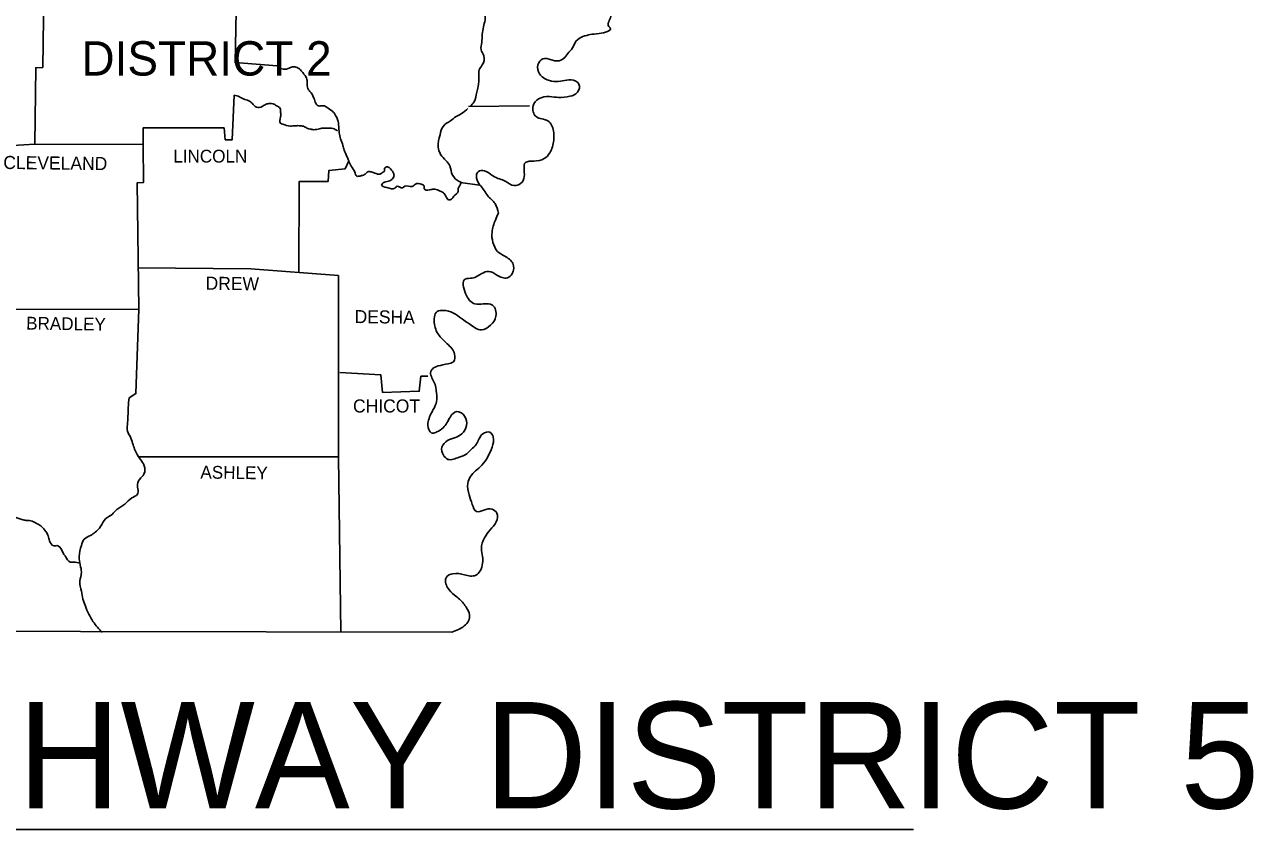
# Model space of a CAD drawing. Extents: x 1212896 to 1368412, y 378476 to 478763.
# Drawn here: x 1348211 to 1368412, y 441567 to 454801 of the extents above; entities that cross this region are included whole.
import ezdxf

# ---------------------------------------------------------------- set-up
doc = ezdxf.new("R2010")
doc.units = 0
doc.layers.add('R_Draft', color=7, linetype='Continuous')

msp = doc.modelspace()

# ---------------------------------------------------------------- linework, layer by layer
at = {"layer": 'R_Draft'}
for p, q in [((1355510, 453452), (1356510, 453467)), ((1355690, 452162), (1355375, 452202)), ((1329763, 441567), (1362824, 441567))]:
    msp.add_line(p, q, dxfattribs=at)
for points in [[(1348540, 456117), (1348510, 454097), (1348395, 454092), (1348380, 452837)], [(1351711, 456139), (1351670, 454177), (1352365, 454122)], [(1351655, 453642), (1351625, 452907), (1351510, 452907), (1351490, 453102), (1350160, 453102), (1350160, 452822)], [(1347650, 452792), (1348380, 452837)], [(1348380, 452837), (1350150, 452827)], [(1350160, 452827), (1350165, 452202), (1350060, 452197), (1350090, 450122)], [(1353540, 452562), (1353480, 452427), (1353215, 452402), (1353200, 452222), (1352725, 452222), (1352720, 450727)], [(1350075, 450802), (1351930, 450787), (1353370, 450677)], [(1353370, 450677), (1353370, 447687), (1353410, 444812)], [(1347830, 450117), (1350090, 450122)], [(1350090, 450122), (1350040, 448732), (1349930, 448662)], [(1353395, 449082), (1354065, 449042), (1354095, 448752), (1354700, 448772), (1354725, 449017), (1354840, 449017)], [(1355235, 444812), (1336910, 444842), (1336900, 448887)], [(1350088, 447692), (1353370, 447692)]]:
    msp.add_lwpolyline(points, dxfattribs=at)
for points in [[(1359445, 458317), (1359330, 458172), (1359160, 458262), (1359160, 458382), (1359185, 458507), (1359125, 458587), (1359020, 458552), (1359020, 458397), (1359010, 458247), (1358980, 458032), (1359050, 457967), (1359210, 457947), (1359325, 457917), (1359395, 457802), (1359390, 457662), (1359335, 457527), (1359255, 457417), (1359130, 457377), (1359030, 457442), (1358990, 457572), (1358945, 457687), (1358860, 457772), (1358770, 457677), (1358750, 457502), (1358755, 457352), (1358755, 457147), (1358885, 457012), (1358965, 456857), (1358940, 456717), (1358845, 456552), (1358805, 456407), (1358765, 456212), (1358770, 455997), (1358735, 455787), (1358665, 455647), (1358535, 455532), (1358450, 455457), (1358380, 455382), (1358345, 455232), (1358320, 455127), (1358225, 455002), (1358150, 454992), (1358090, 455042), (1358070, 455127), (1358070, 455212), (1358030, 455297), (1357905, 455332), (1357805, 455327), (1357760, 455257), (1357825, 455062), (1357850, 454937), (1357815, 454767), (1357835, 454747), (1357655, 454652), (1357510, 454637), (1357390, 454602), (1357275, 454527), (1357220, 454417), (1357140, 454327), (1357070, 454242), (1356975, 454202), (1356870, 454222), (1356730, 454237), (1356650, 454137), (1356675, 453992), (1356770, 453907), (1356910, 453867), (1357055, 453877), (1357195, 453892), (1357325, 453822), (1357300, 453687), (1357175, 453622), (1356990, 453602), (1356840, 453617), (1356660, 453577), (1356570, 453462), (1356620, 453287), (1356815, 453217), (1356905, 453052), (1356910, 452897), (1356845, 452692), (1356755, 452597), (1356580, 452557), (1356445, 452532), (1356425, 452302), (1356365, 452187), (1356260, 452152), (1356110, 452227), (1356020, 452262), (1355910, 452312), (1355770, 452397), (1355665, 452382), (1355695, 452162), (1355705, 452152), (1355825, 451987), (1355945, 451857), (1356000, 451702)], [(1359445, 458317), (1359330, 458172), (1359160, 458262), (1359160, 458382), (1359185, 458507), (1359125, 458587), (1359020, 458552), (1359020, 458397), (1359010, 458247), (1358980, 458032), (1359050, 457967), (1359210, 457947), (1359325, 457917), (1359395, 457802), (1359390, 457662), (1359335, 457527), (1359255, 457417), (1359130, 457377), (1359030, 457442), (1358990, 457572), (1358945, 457687), (1358860, 457772), (1358770, 457677), (1358750, 457502), (1358755, 457352), (1358755, 457147), (1358885, 457012), (1358965, 456857), (1358940, 456717), (1358845, 456552), (1358805, 456407), (1358765, 456212), (1358770, 455997), (1358735, 455787), (1358665, 455647), (1358535, 455532), (1358450, 455457), (1358380, 455382), (1358345, 455232), (1358320, 455127), (1358225, 455002), (1358150, 454992), (1358090, 455042), (1358070, 455127), (1358070, 455212), (1358030, 455297), (1357905, 455332), (1357805, 455327), (1357760, 455257), (1357825, 455062), (1357850, 454937), (1357815, 454767), (1357835, 454747), (1357655, 454652), (1357510, 454637), (1357390, 454602), (1357275, 454527), (1357220, 454417), (1357140, 454327), (1357070, 454242), (1356975, 454202), (1356870, 454222), (1356730, 454237), (1356650, 454137), (1356675, 453992), (1356770, 453907), (1356910, 453867), (1357055, 453877), (1357195, 453892), (1357325, 453822), (1357300, 453687), (1357175, 453622), (1356990, 453602), (1356840, 453617), (1356660, 453577), (1356570, 453462), (1356620, 453287), (1356815, 453217), (1356905, 453052), (1356910, 452897), (1356845, 452692), (1356755, 452597), (1356580, 452557), (1356445, 452532), (1356425, 452302), (1356365, 452187), (1356260, 452152), (1356110, 452227), (1356020, 452262), (1355910, 452312), (1355770, 452397), (1355665, 452382), (1355695, 452162), (1355705, 452152), (1355825, 451987), (1355945, 451857), (1356000, 451702)], [(1355535, 453452), (1355600, 453532), (1355645, 453687), (1355665, 453782), (1355680, 453947), (1355685, 454057), (1355735, 454137), (1355760, 454287), (1355715, 454387), (1355725, 454507), (1355735, 454642), (1355755, 454762), (1355780, 454877), (1355780, 454952), (1355715, 455052), (1355615, 455117), (1355535, 455142), (1355485, 455177), (1355415, 455237), (1355345, 455357), (1355305, 455402), (1355225, 455507), (1355145, 455567), (1355095, 455702), (1355015, 455797), (1354905, 455837), (1354825, 455922), (1354795, 456052), (1354745, 456132), (1354675, 456182), (1354560, 456252), (1354475, 456302), (1354450, 456417), (1354400, 456472), (1354280, 456502), (1354265, 456707)], [(1352365, 454122), (1352440, 454072), (1352545, 454077), (1352615, 454107), (1352670, 454102), (1352745, 454057), (1352795, 453997), (1352830, 453952), (1352855, 453882), (1352855, 453817), (1352880, 453727), (1352910, 453692), (1352950, 453627), (1352975, 453567), (1352990, 453527), (1353045, 453462), (1353095, 453467), (1353140, 453462), (1353200, 453427), (1353290, 453357), (1353305, 453337), (1353365, 453207), (1353375, 453127), (1353385, 453022), (1353405, 452922), (1353445, 452812), (1353465, 452737), (1353510, 452632), (1353540, 452562), (1353580, 452472), (1353640, 452372), (1353665, 452312), (1353750, 452317), (1353810, 452342), (1353855, 452382), (1353910, 452377), (1353970, 452357), (1354050, 452342), (1354100, 452372), (1354125, 452392), (1354130, 452437), (1354175, 452462), (1354225, 452427), (1354280, 452347), (1354280, 452297), (1354260, 452267), (1354195, 452227), (1354105, 452197), (1354080, 452162), (1354165, 452122), (1354300, 452112), (1354335, 452142), (1354425, 452117), (1354460, 452142), (1354580, 452137), (1354635, 452177), (1354745, 452172), (1354780, 452147), (1354780, 452102), (1354870, 452082), (1354935, 452097), (1355020, 452072), (1355095, 452032), (1355135, 451977), (1355185, 451917), (1355230, 451932), (1355265, 451977), (1355340, 452057), (1355340, 452107), (1355360, 452142), (1355385, 452192)], [(1351655, 453642), (1351745, 453612), (1351810, 453577), (1351895, 453547), (1351950, 453507), (1352025, 453442), (1352115, 453452), (1352180, 453492), (1352245, 453502), (1352295, 453497), (1352350, 453467), (1352410, 453422), (1352420, 453357), (1352420, 453282), (1352420, 453177), (1352455, 453162), (1352580, 453132), (1352665, 453137), (1352745, 453137), (1352810, 453122), (1352865, 453092), (1352905, 453082), (1352965, 453072), (1353015, 453077), (1353100, 453097), (1353150, 453097), (1353230, 453097), (1353280, 453092), (1353355, 453052)], [(1355390, 452207), (1355355, 452222), (1355245, 452327), (1355200, 452477), (1355140, 452562), (1355050, 452667), (1355010, 452787), (1355040, 452987), (1355095, 453132), (1355210, 453217), (1355305, 453287), (1355395, 453337), (1355500, 453422)], [(1356000, 451702), (1355950, 451587), (1355895, 451387), (1355910, 451217), (1355985, 451072), (1356105, 450992), (1356235, 450877), (1356225, 450702), (1356150, 450637), (1355975, 450682), (1355840, 450742), (1355725, 450707), (1355570, 450632), (1355455, 450617), (1355460, 450377), (1355615, 450207), (1355750, 450207), (1355905, 450187), (1355960, 450007), (1355870, 449857), (1355720, 449782), (1355530, 449872), (1355395, 449967), (1355260, 450057), (1355090, 450102), (1354995, 450082), (1354950, 449872), (1355030, 449682), (1355160, 449552), (1355280, 449382), (1355260, 449257), (1355170, 449222), (1355010, 449187), (1354915, 449137), (1354890, 449097), (1354940, 448927), (1354985, 448742), (1354985, 448602), (1354930, 448472), (1354845, 448272), (1354855, 448142), (1354915, 448082), (1354990, 448102), (1355090, 448172), (1355155, 448252), (1355210, 448352), (1355315, 448437), (1355445, 448362), (1355475, 448207), (1355400, 448072), (1355295, 448012), (1355165, 447962), (1355070, 447852), (1355095, 447722), (1355170, 447652), (1355355, 447687), (1355480, 447742), (1355550, 447812), (1355635, 447897), (1355680, 447982), (1355745, 448072), (1355860, 448097), (1355915, 448022), (1355895, 447852), (1355825, 447692), (1355730, 447557), (1355625, 447462), (1355495, 447257), (1355520, 447067), (1355570, 446912), (1355640, 446792), (1355760, 446817), (1355895, 446832), (1355975, 446767), (1355965, 446627), (1355865, 446492), (1355770, 446362), (1355720, 446182), (1355740, 446057), (1355740, 445942), (1355700, 445817), (1355630, 445747), (1355445, 445752), (1355250, 445772), (1355145, 445712), (1355165, 445542), (1355280, 445417), (1355360, 445352), (1355475, 445212), (1355525, 445097), (1355510, 444997), (1355440, 444912), (1355235, 444812)], [(1356000, 451702), (1355950, 451587), (1355895, 451387), (1355910, 451217), (1355985, 451072), (1356105, 450992), (1356235, 450877), (1356225, 450702), (1356150, 450637), (1355975, 450682), (1355840, 450742), (1355725, 450707), (1355570, 450632), (1355455, 450617), (1355460, 450377), (1355615, 450207), (1355750, 450207), (1355905, 450187), (1355960, 450007), (1355870, 449857), (1355720, 449782), (1355530, 449872), (1355395, 449967), (1355260, 450057), (1355090, 450102), (1354995, 450082), (1354950, 449872), (1355030, 449682), (1355160, 449552), (1355280, 449382), (1355260, 449257), (1355170, 449222), (1355010, 449187), (1354915, 449137), (1354890, 449097), (1354940, 448927), (1354985, 448742), (1354985, 448602), (1354930, 448472), (1354845, 448272), (1354855, 448142), (1354915, 448082), (1354990, 448102), (1355090, 448172), (1355155, 448252), (1355210, 448352), (1355315, 448437), (1355445, 448362), (1355475, 448207), (1355400, 448072), (1355295, 448012), (1355165, 447962), (1355070, 447852), (1355095, 447722), (1355170, 447652), (1355355, 447687), (1355480, 447742), (1355550, 447812), (1355635, 447897), (1355680, 447982), (1355745, 448072), (1355860, 448097), (1355915, 448022), (1355895, 447852), (1355825, 447692), (1355730, 447557), (1355625, 447462), (1355495, 447257), (1355520, 447067), (1355570, 446912), (1355640, 446792), (1355760, 446817), (1355895, 446832), (1355975, 446767), (1355965, 446627), (1355865, 446492), (1355770, 446362), (1355720, 446182), (1355740, 446057), (1355740, 445942), (1355700, 445817), (1355630, 445747), (1355445, 445752), (1355250, 445772), (1355145, 445712), (1355165, 445542), (1355280, 445417), (1355360, 445352), (1355475, 445212), (1355525, 445097), (1355510, 444997), (1355440, 444912), (1355235, 444812)], [(1349930, 448662), (1349915, 448507), (1349910, 448362), (1349900, 448222), (1349900, 448117), (1349960, 448002), (1349995, 447892), (1350030, 447797), (1350100, 447672), (1350165, 447577), (1350185, 447442), (1350145, 447372), (1350070, 447267), (1350065, 447077), (1349975, 447017), (1349860, 446917), (1349795, 446872), (1349725, 446827), (1349650, 446747), (1349540, 446672), (1349460, 446547), (1349370, 446452), (1349295, 446402), (1349190, 446337), (1349145, 446237), (1349110, 446052), (1349125, 445917), (1349145, 445797), (1349120, 445647), (1349145, 445482), (1349170, 445352), (1349210, 445237), (1349265, 445107), (1349335, 444987), (1349485, 444802)], [(1344945, 447507), (1345025, 447562), (1345100, 447592), (1345175, 447577), (1345255, 447567), (1345325, 447577), (1345415, 447562), (1345490, 447517), (1345575, 447482), (1345660, 447482), (1345735, 447482), (1345800, 447437), (1345920, 447442), (1346020, 447482), (1346120, 447512), (1346255, 447527), (1346375, 447442), (1346460, 447372), (1346530, 447292), (1346580, 447202), (1346635, 447152), (1346725, 447117), (1346795, 447102), (1346880, 447077), (1346925, 447057), (1346965, 446962), (1347030, 446832), (1347155, 446787), (1347310, 446847), (1347435, 446882), (1347525, 446912), (1347580, 446932), (1347630, 446937), (1347615, 446947), (1347675, 446962), (1347730, 446922), (1347765, 446867), (1347825, 446787), (1347880, 446717), (1347935, 446692), (1347990, 446722), (1348065, 446697), (1348130, 446672), (1348205, 446652), (1348270, 446647), (1348355, 446627), (1348420, 446592), (1348480, 446557), (1348540, 446492), (1348600, 446392), (1348620, 446312), (1348690, 446232), (1348755, 446232), (1348850, 446102), (1348885, 446052), (1348960, 445962), (1349015, 445962), (1349120, 445942)]]:
    msp.add_spline(points, degree=3, dxfattribs=at)

# ---------------------------------------------------------------- texts
for s, height, p in [('DISTRICT 2', 565, (1349145, 453962)), ('LINCOLN', 210, (1350655, 452532)), ('CHICOT', 215, (1353610, 448422)), ('ARKANSAS HIGHWAY DISTRICT 5', 1750, (1330542, 441912))]:
    msp.add_text(s, height=height, dxfattribs=at).set_placement(p)
for s, height, rotation, p in [('CLEVELAND', 215, 359.3376, (1347860, 452427)), ('DREW', 215, 359.2258, (1351185, 450442)), ('DESHA', 215, 359.3704, (1353635, 449892)), ('BRADLEY', 210, 359.1449, (1348235, 449787)), ('ASHLEY', 210, 359.2361, (1351100, 447337))]:
    msp.add_text(s, height=height, rotation=rotation, dxfattribs=at).set_placement(p)

doc.saveas('drawing.dxf')
